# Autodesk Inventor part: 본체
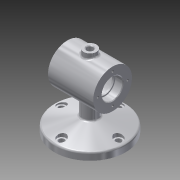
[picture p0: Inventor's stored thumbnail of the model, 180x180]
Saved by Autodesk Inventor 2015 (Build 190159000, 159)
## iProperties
Created: 2018-12
Part Number: 본체
Material: 알루미늄 6061
Document SubType Name: Modeling
Designer: now
Density: 2.7 g/cm^3
Appearance: 알루미늄 - 평지
Mass: 685.089 g
Surface Area: 555.482 cm^2
Volume: 253.737 cm^3
Author: now
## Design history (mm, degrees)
sketch "스케치1"
  geometry: C1 r 30 at (0, 0); 1 further point
  constraints: 1 centre point, 1 coincident
  dimensions: "d0" = 60 diameter of C1
extrude "돌출1" new body sketch "스케치1" stored distance "d1" = 70; taper "d2" = 0 deg
sketch "스케치2"
  geometry: L1 (35, 30)-(35, -30) reference; L2 (35, -30)-(-35, -30) reference; L3 (-35, -30)-(-35, 30) reference; L4 (-35, 30)-(35, 30) reference; L5 (35, -30)-(35, 30) reference; L6 (35, 0)-(23, 0); L7 (23, 0)-(23, 15.7); L8 (23.3, 16)-(35, 16); L9 (35, 16)-(35, 0); A1 r 0.3 centre (23.3, 15.7) between (23.3, 16) and (23, 15.7); 2 further points
  constraints: 8 end point, 2 parallel, 2 point on circle, 2 point on line, 2 tangent, 1 centre point, 1 horizontal, 1 midpoint, 1 perpendicular
  dimensions: "d3" = 16 distance of L6.end point (23, 16); "d4" = 12 distance of L6.start L6.end; "d6" = 0.3 radius of A1
revolve "회전1" sketch "스케치2" stored, may be unused: angle "d5" = 90 deg
sketch "스케치3"
  geometry: L1 (23.3, -16)-(35, -16) reference; L2 (35, -16)-(35, -30) reference; L3 (35, -30)-(-35, -30) reference; L4 (-35, -30)-(-35, 30) reference; L5 (-35, 30)-(35, 30) reference; L6 (35, 30)-(35, 16) reference; L7 (35, 16)-(23.3, 16) reference; L8 (23, 15.7)-(23, -15.7) reference; L9 (23, 15.7)-(23, -15.7) reference; L10 (23, 0)-(20, 0); L11 (20, 0)-(20, 14); L12 (20, 14)-(23, 14); L13 (23, 14)-(23, 0); A1 r 0.3 centre (23.3, 15.7) between (23.3, 16) and (23, 15.7) reference; A2 r 0.3 centre (23.3, -15.7) between (23, -15.7) and (23.3, -16) reference; 1 further point
  constraints: 8 end point, 2 parallel, 1 horizontal, 1 midpoint, 1 perpendicular
  dimensions: "d7" = 3 distance of L10.start L10.end; "d8" = 14 distance of L10.end L11.end
revolve "회전2" sketch "스케치3" stored, may be unused: angle "d9" = 90 deg
sketch "스케치4"
  geometry: L1 (23.3, -16)-(35, -16) reference; L2 (35, -16)-(35, -30) reference; L3 (35, -30)-(-35, -30) reference; L4 (-35, -30)-(-35, 30) reference; L5 (-35, 30)-(35, 30) reference; L6 (35, 30)-(35, 16) reference; L7 (35, 16)-(23.3, 16) reference; L8 (23, 15.7)-(23, 14) reference; L9 (23, 14)-(20, 14) reference; L10 (20, 14)-(20, -14) reference; L11 (20, -14)-(23, -14) reference; L12 (23, -14)-(23, -15.7) reference; L13 (20, 0)-(-20, 0); L14 (-20, 0)-(-20, 22); L15 (-17, 25)-(17, 25); L16 (20, 22)-(20, 0); A1 r 0.3 centre (23.3, 15.7) between (23.3, 16) and (23, 15.7) reference; A2 r 0.3 centre (23.3, -15.7) between (23, -15.7) and (23.3, -16) reference; A3 r 3 centre (17, 22) between (20, 22) and (17, 25); A4 r 3 centre (-17, 22) between (-17, 25) and (-20, 22); 2 further points
  constraints: 8 end point, 4 point on circle, 4 tangent, 2 centre point, 2 parallel, 2 point on line, 1 equal radius, 1 horizontal, 1 midpoint, 1 perpendicular
  dimensions: "d10" = 40 distance of L13.start L13.end; "d11" = 25 distance of L13.end point (-20, 25); "d12" = 3 radius of A3
revolve "회전3" sketch "스케치4" stored, may be unused: angle "d13" = 90 deg
sketch "스케치5"
  geometry: L1 (23.3, -16)-(35, -16) reference; L2 (35, -16)-(35, -30) reference; L3 (35, -30)-(-35, -30) reference; L4 (-35, -30)-(-35, 30) reference; L5 (-35, 30)-(35, 30) reference; L6 (35, 30)-(35, 16) reference; L7 (35, 16)-(23.3, 16) reference; L8 (23, 15.7)-(23, 14) reference; L9 (23, 14)-(20, 14) reference; L10 (20, 14)-(20, 22) reference; L11 (17, 25)-(-17, 25) reference; L12 (-20, 22)-(-20, -22) reference; L13 (-17, -25)-(17, -25) reference; L14 (20, -22)-(20, -14) reference; L15 (20, -14)-(23, -14) reference; L16 (23, -14)-(23, -15.7) reference; L17 (-20, 22)-(-20, -22) reference; L18 (-20, 0)-(-23, 0); L19 (-23, 0)-(-23, 14); L20 (-23, 14)-(-20, 14); L21 (-20, 14)-(-20, 0); A1 r 0.3 centre (23.3, 15.7) between (23.3, 16) and (23, 15.7) reference; A2 r 3 centre (17, 22) between (20, 22) and (17, 25) reference; A3 r 3 centre (-17, 22) between (-17, 25) and (-20, 22) reference; A4 r 3 centre (-17, -22) between (-20, -22) and (-17, -25) reference; A5 r 3 centre (17, -22) between (17, -25) and (20, -22) reference; A6 r 0.3 centre (23.3, -15.7) between (23, -15.7) and (23.3, -16) reference; 1 further point
  constraints: 8 end point, 2 parallel, 1 horizontal, 1 midpoint, 1 perpendicular
  dimensions: "d14" = 3 distance of L18.start L18.end; "d15" = 14 distance of L18.end L19.end
revolve "회전4" sketch "스케치5" stored, may be unused: angle "d16" = 90 deg
sketch "스케치6"
  geometry: L1 (23.3, -16)-(35, -16) reference; L2 (35, -16)-(35, -30) reference; L3 (35, -30)-(-35, -30) reference; L4 (-35, -30)-(-35, 30) reference; L5 (-35, 30)-(35, 30) reference; L6 (35, 30)-(35, 16) reference; L7 (35, 16)-(23.3, 16) reference; L8 (23, 15.7)-(23, 14) reference; L9 (23, 14)-(20, 14) reference; L10 (20, 14)-(20, 22) reference; L11 (17, 25)-(-17, 25) reference; L12 (-20, 22)-(-20, 14) reference; L13 (-20, 14)-(-23, 14) reference; L14 (-23, 14)-(-23, -14) reference; L15 (-23, -14)-(-20, -14) reference; L16 (-20, -14)-(-20, -22) reference; L17 (-17, -25)-(17, -25) reference; L18 (20, -22)-(20, -14) reference; L19 (20, -14)-(23, -14) reference; L20 (23, -14)-(23, -15.7) reference; L21 (-35, 30)-(-35, -30) reference; L22 (-23, 0)-(-35, 0); L23 (-35, 0)-(-35, 16); L24 (-35, 16)-(-23.3, 16); L25 (-23, 15.7)-(-23, 0); A1 r 0.3 centre (23.3, 15.7) between (23.3, 16) and (23, 15.7) reference; A2 r 3 centre (17, 22) between (20, 22) and (17, 25) reference; A3 r 3 centre (-17, 22) between (-17, 25) and (-20, 22) reference; A4 r 3 centre (-17, -22) between (-20, -22) and (-17, -25) reference; A5 r 3 centre (17, -22) between (17, -25) and (20, -22) reference; A6 r 0.3 centre (23.3, -15.7) between (23, -15.7) and (23.3, -16) reference; A7 r 0.3 centre (-23.3, 15.7) between (-23, 15.7) and (-23.3, 16); 2 further points
  constraints: 8 end point, 3 point on line, 2 parallel, 2 point on circle, 2 tangent, 1 centre point, 1 horizontal, 1 midpoint, 1 perpendicular
  dimensions: "d17" = 16 distance of point (-23, 16) L22.start; "d18" = 0.3 radius of A7
revolve "회전5" sketch "스케치6" stored, may be unused: angle "d19" = 90 deg
chamfer "모따기1" distance "d20" = 1; stored, may be unused: second distance "d21" = 2, angle "d22" = 45 deg
sketch "스케치7"
  geometry: C1 r 30 at (0, 0) reference; 1 further point
  constraints: 1 horizontal alignment
  dimensions: "d23" = 23 distance of point (23, 0) C1.centre
hole "구멍1" sketch "스케치7" at (23, 0) diameter "d24" = 3.242; stored, may be unused: countersink angle "d28" = 90 deg, drill point angle "d30" = 118 deg; dims "d25" = 8, "d26" = 4, "d27" = 2, "d29" = 10
node "작업 평면1"
sketch "스케치8"
  geometry: L1 (-35, 30)-(-35, -30) reference; C1 r 10 at (0, 0); 2 further points
  constraints: 1 centre point, 1 horizontal alignment, 1 midpoint
  dimensions: "d35" = 20 diameter of C1; "d36" = 35 distance from line of C1.centre L1
extrude "돌출2" join sketch "스케치8" stored distance "d37" = 70; taper "d38" = 0 deg
sketch "스케치9"
  geometry: C1 r 10 at (0, 0) reference; C2 r 5 at (0, 0)
  constraints: 1 centre point, 1 coincident
  dimensions: "d39" = 10 diameter of C2
extrude "돌출3" cut sketch "스케치9" stored distance "d40" = 70; taper "d41" = 0 deg
chamfer "모따기2" distance "d42" = 1; stored, may be unused: second distance "d43" = 2, angle "d44" = 45 deg
node "작업 평면2"
sketch "스케치10"
  geometry: C1 r 55 at (0, 0); 1 further point
  constraints: 1 centre point, 1 coincident
  dimensions: "d46" = 110 diameter of C1
extrude "돌출4" join sketch "스케치10" distance "d47" = 11; taper "d48" = 0 deg
sketch "스케치11"
  geometry: L1 (35, 17)-(34, 16) reference; L2 (34, 16)-(23.3, 16) reference; L3 (23, 15.7)-(23, 14) reference; L4 (23, 14)-(20, 14) reference; L5 (20, 14)-(20, 22) reference; L6 (17, 25)-(5, 25) reference; L7 (5, 25)-(5, 36) reference; L8 (5, 36)-(6, 37) reference; L9 (6, 37)-(10, 37) reference; L10 (10, 37)-(10, 30) reference; L11 (10, 30)-(35, 30) reference; L12 (35, 30)-(35, 24.621) reference; L13 (35, 24.621)-(25, 24.621) reference; L14 (25, 24.621)-(24.026, 23) reference; L15 (24.026, 23)-(25, 21.379) reference; L16 (25, 21.379)-(35, 21.379) reference; L17 (35, 21.379)-(35, 17) reference; L18 (-35, -17)-(-34, -16) reference; L19 (-34, -16)-(-23.3, -16) reference; L20 (-23, -15.7)-(-23, -14) reference; L21 (-23, -14)-(-20, -14) reference; L22 (-20, -14)-(-20, -22) reference; L23 (-17, -25)-(17, -25) reference; L24 (20, -22)-(20, -14) reference; L25 (20, -14)-(23, -14) reference; L26 (23, -14)-(23, -15.7) reference; L27 (23.3, -16)-(34, -16) reference; L28 (34, -16)-(35, -17) reference; L29 (35, -17)-(35, -21.379) reference; L30 (35, -21.379)-(25, -21.379) reference; L31 (25, -21.379)-(24.026, -23) reference; L32 (24.026, -23)-(25, -24.621) reference; L33 (25, -24.621)-(35, -24.621) reference; L34 (35, -24.621)-(35, -30) reference; L35 (35, -30)-(-35, -30) reference; L36 (-35, -30)-(-35, -24.621) reference; L37 (-35, -24.621)-(-25, -24.621) reference; L38 (-25, -24.621)-(-24.026, -23) reference; L39 (-24.026, -23)-(-25, -21.379) reference; L40 (-25, -21.379)-(-35, -21.379) reference; L41 (-35, -21.379)-(-35, -17) reference; L42 (-34, 16)-(-35, 17) reference; L43 (-35, 17)-(-35, 21.379) reference; L44 (-35, 21.379)-(-25, 21.379) reference; L45 (-25, 21.379)-(-24.026, 23) reference; L46 (-24.026, 23)-(-25, 24.621) reference; L47 (-25, 24.621)-(-35, 24.621) reference; L48 (-35, 24.621)-(-35, 30) reference; L49 (-35, 30)-(-10, 30) reference; L50 (-10, 30)-(-10, 37) reference; L51 (-10, 37)-(-6, 37) reference; L52 (-6, 37)-(-5, 36) reference; L53 (-5, 36)-(-5, 25) reference; L54 (-5, 25)-(-17, 25) reference; L55 (-20, 22)-(-20, 14) reference; L56 (-20, 14)-(-23, 14) reference; L57 (-23, 14)-(-23, 15.7) reference; L58 (-23.3, 16)-(-34, 16) reference; L59 (-55, -75)-(-55, -64) reference; L60 (-55, -64)-(55, -64) reference; L61 (55, -64)-(55, -75) reference; L62 (55, -75)-(-55, -75) reference; L63 (0, -64)-(0, -49.263); L64 (55, -64)-(0, -49.263); A1 r 0.3 centre (23.3, 15.7) between (23.3, 16) and (23, 15.7) reference; A2 r 3 centre (17, 22) between (20, 22) and (17, 25) reference; A3 r 0.3 centre (-23.3, -15.7) between (-23.3, -16) and (-23, -15.7) reference; A4 r 3 centre (-17, -22) between (-20, -22) and (-17, -25) reference; A5 r 3 centre (17, -22) between (17, -25) and (20, -22) reference; A6 r 0.3 centre (23.3, -15.7) between (23, -15.7) and (23.3, -16) reference; A7 r 3 centre (-17, 22) between (-17, 25) and (-20, 22) reference; A8 r 0.3 centre (-23.3, 15.7) between (-23, 15.7) and (-23.3, 16) reference; 2 further points
  constraints: 4 end point, 2 midpoint, 1 vertical alignment
  dimensions: "d50" = 75 deg angle of L64 L61
revolve "회전6" sketch "스케치11" stored, may be unused: angle "d51" = 90 deg
sketch "스케치12"
  geometry: C1 r 55 at (0, 0) reference; C2 r 12 at (0, 0)
  constraints: 1 centre point, 1 coincident
  dimensions: "d52" = 24 diameter of C2
extrude "돌출5" join sketch "스케치12" stored distance "d53" = 11; taper "d54" = 0 deg
sketch "스케치13"
  geometry: C1 r 55 at (0, 0) reference; 1 further point
  constraints: 1 horizontal alignment
  dimensions: "d55" = 44 distance of point (-44, 0) C1.centre
hole "구멍2" sketch "스케치13" at (-44, 0) diameter "d56" = 9; stored, may be unused: countersink angle "d60" = 90 deg, drill point angle "d62" = 0 deg; dims "d57" = 8, "d58" = 14, "d59" = 2, "d61" = 10
sketch "스케치14"
  geometry: C1 r 4.5 at (0, 0) reference; C2 r 7 at (0, 0); 1 further point
  constraints: 1 centre point, 1 coincident
  dimensions: "d63" = 14 diameter of C2
extrude "돌출6" cut sketch "스케치14" stored distance "d64" = 11; taper "d65" = 0 deg
fillet "모깎기1" dims "d69" = 3
fillet "모깎기2" dims "d70" = 3
node "작업 평면3"
sketch "스케치15"
  geometry: L1 (-35, 30)-(-35, -30) reference; 2 further points
  constraints: 1 other
  dimensions: "d72" = 35 distance from line of L1 point (0, 0); "d73" = 30 vertical distance of L1.start point (0, 0)
feature "엠보싱1" sketch "스케치15" dims "d2" = 0, "d74" = 0.5, "d75" = 0
node "솔리드1"
pattern_circular "원형 패턴1" dims angle "d32" = 360 deg
mirror "대칭1"
pattern_circular "원형 패턴2" dims angle "d67" = 360 deg
node "절단 모서리 투영1"
node "절단 모서리 투영2"
node "절단 모서리 투영3"
node "절단 모서리 투영4"
node "절단 모서리 투영5"
node "절단 모서리 투영6"
other parameters: "d34" = 37, "d45" = -75, "d71" = 60.25
